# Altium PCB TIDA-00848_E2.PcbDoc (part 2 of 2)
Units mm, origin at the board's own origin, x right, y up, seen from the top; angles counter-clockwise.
Board outline 40 x 87.63 mm, 2 copper layers (Top Layer, Bottom Layer), stack 0.98 mm thick; 101 components, 66 nets, 314 pads, 292 vias.
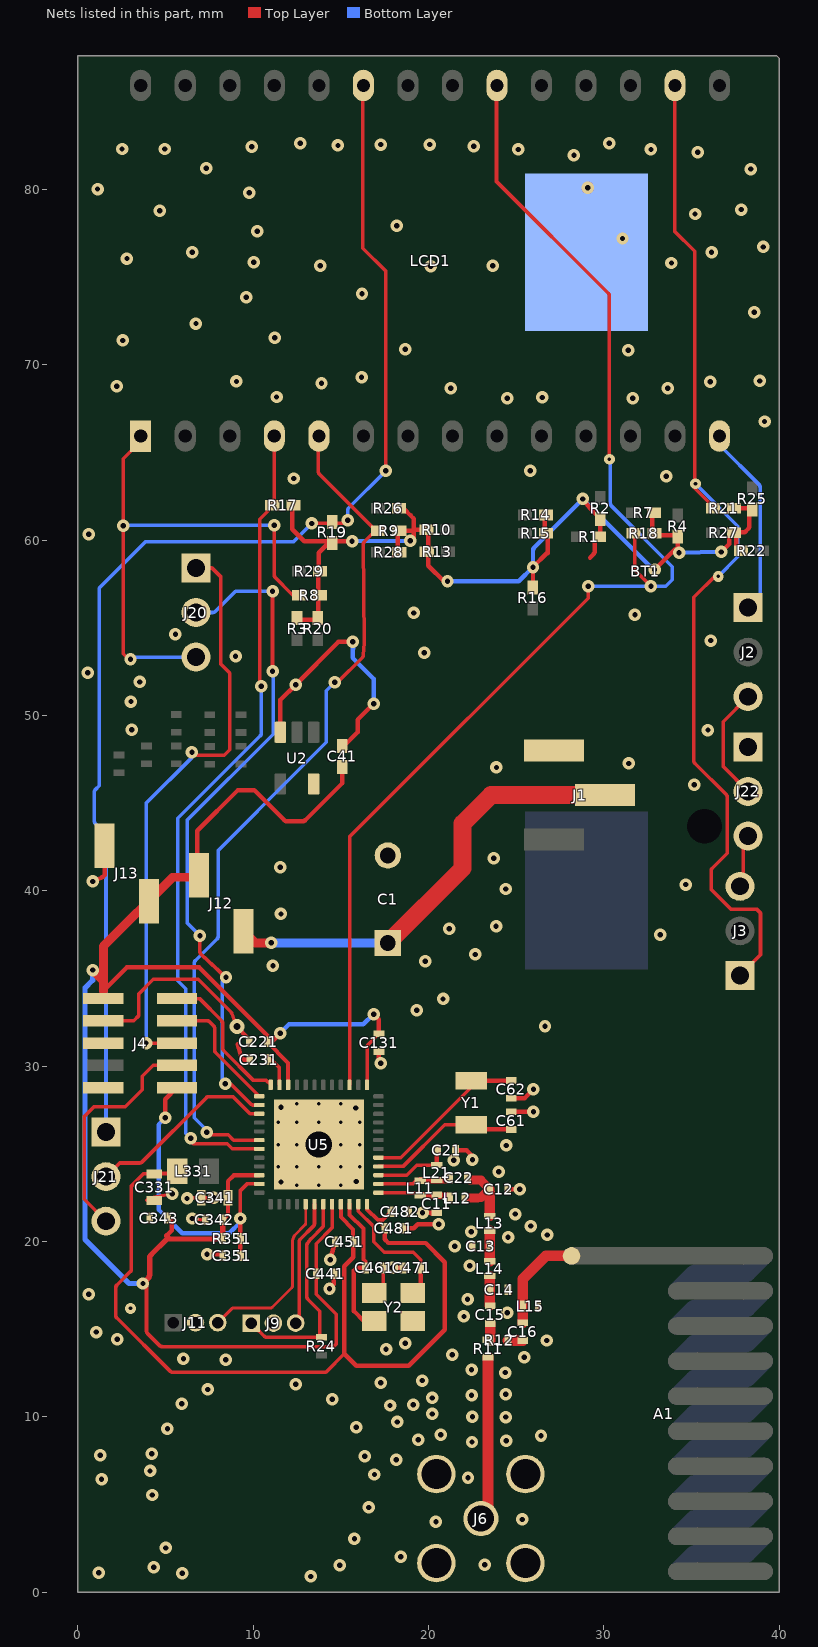
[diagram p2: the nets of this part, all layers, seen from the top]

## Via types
v1: diameter 0.711, hole 0.305, Top Layer to Bottom Layer, 239 vias
v2: diameter 0.5, hole 0.2, Top Layer to Bottom Layer, 21 vias
v3: diameter 1, hole 0.38, Top Layer to Bottom Layer, 19 vias
v4: diameter 0.61, hole 0.203, Top Layer to Bottom Layer, tented both sides, 8 vias
v5: diameter 3.175, hole 3.175, Top Layer to Bottom Layer, 2 vias
v6: diameter 0.864, hole 0.406, Top Layer to Bottom Layer, 1 vias
v7: diameter 1.27, hole 0.711, Top Layer to Bottom Layer, 1 vias
v8: diameter 1.9, hole 1.5, Top Layer to Bottom Layer, 1 vias

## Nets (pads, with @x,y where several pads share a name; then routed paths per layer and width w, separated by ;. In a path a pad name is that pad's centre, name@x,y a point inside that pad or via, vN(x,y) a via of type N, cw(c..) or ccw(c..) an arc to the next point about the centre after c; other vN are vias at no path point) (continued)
DIO_20: LCD1.5 R9.1 U5.30 | length 48.9
  Top Layer w0.203: v1@7.564,26.091 8.565,26.091 8.876,25.781 U5.30@10.345,25.781 ; LCD1.5@13.741,65.946 13.716,65.921 13.716,63.914 ccw(c13.919,63.914) 13.757,63.792 ccw(c13.919,63.914) 13.775,63.771 17.132,60.414 17.132,60.35 16.764,60.35 16.338,59.925 ccw(c16.482,59.781) 16.279,59.78 16.329,54.209 cw(c15.672,54.204) 16.328,54.161 16.281,53.437 cw(c16.078,53.45) 16.222,53.306 14.808,51.892 v1(14.656,51.892)
  Bottom Layer w0.203: v1@7.315,26.264 7.264,26.314 7.264,26.43 6.629,27.065 6.629,35.866 cw(c6.833,35.866) 6.67,35.988 cw(c6.833,35.866) 6.689,36.01 7.942,37.263 ccw(c7.798,37.406) 7.96,37.284 ccw(c7.798,37.406) 8.001,37.406 8.001,42.304 9.871,44.174 9.873,44.174 10.258,44.559 10.258,44.562 14.173,48.477 14.173,51.41 v1(14.656,51.892)
  other v1: 7.341,26.238
DIO_21: LCD1.4 R17.2 U5.31 | length 46.6
  Top Layer w0.203: 6.591,25.565 8.522,25.565 8.806,25.281 U5.31@10.345,25.281 ; v1(10.465,51.664) 10.38,51.749 10.38,61.205 11.176,62.001 11.189,62.014 11.189,65.933 LCD1.4@11.201,65.946
  Bottom Layer w0.203: v1(6.426,25.883) 6.147,26.162 6.147,34.418 5.691,34.874 5.691,44.138 10.406,48.852 ; 10.406,48.853 ccw(c10.262,48.995) 10.424,48.873 ccw(c10.262,48.995) 10.465,48.995 v1(10.465,51.664)
DIO_30: J9.1 R24.2 U5.43 | length 12.7
  Top Layer w0.203: J9.1@10.008,15.519 10.101,15.121 10.634,14.588 ccw(c10.778,14.732) 10.656,14.569 ccw(c10.778,14.732) 10.778,14.529 13.792,14.529 R24.2@13.894,14.529 13.792,14.63 13.792,16.027 13.115,16.704 ; 13.114,16.706 cw(c13.259,16.848) 13.056,16.848 13.056,19.779 cw(c13.259,19.779) 13.096,19.901 cw(c13.259,19.779) 13.098,19.903 13.271,20.125 cw(c13.589,19.877) 13.304,20.162 13.935,20.793 ccw(c13.792,20.937) 13.995,20.937 U5.43@13.995,22.131
GND: BT1.2 C1.2 C11.1 C12.2 C13.2 C14.2 C21.1 C41.2 C61.2 C62.2 C131.2 C221.2 C231.2 C331.2 C341.2 C342.2 C343.2 C351.2 C441.2 C451.2 C461.2 C471.2 C481.2 C482.2 J4.3 J4.5 J4.9 J6.2 J6.3 J6.4 J6.5 J9.2 J11.2 J13.2 J22.1 L15.1 U2.3 U5.49 Y2.2 Y2.4 | length 48.1
  Top Layer w0.2: Y2.4@16.909,17.056 17.424,17.572 C461.2@17.424,18.491 v1(17.932,18.491)
  Top Layer w0.203: J4.3@1.448,32.588 3.175,32.588 3.48,32.893 3.48,34.138 4.293,34.95 6.858,34.95 8.739,33.069 ; C331.2@3.937,22.352 4.032,22.447 4.073,22.479 cw(c4.176,22.304) 4.141,22.504 v1(5.385,22.722) ; v1(6.223,22.454) 6.274,22.504 C341.2@7.036,22.504 v1(7.747,22.504) v1@7.798,22.504 ; v1(6.528,21.311) 7.01,21.234 ; 8.74,33.068 cw(c8.596,32.925) 8.786,32.997 v6(9.068,32.258)
  Top Layer w0.254: v1(0.838,40.538) 1.37,40.766 ccw(c1.27,40.999) 1.449,40.819 1.524,40.894 J13.2@1.524,42.583 ; v1(7.366,19.279) 8.191,19.279 C351.2@8.255,19.177 ; v6(9.068,32.258) 9.716,31.572 C221.2@9.779,31.394 ; 9.119,31.242 9.306,30.565 ccw(c9.55,30.632) 9.371,30.453 9.445,30.378 C231.2@9.804,30.378 ; U2.3@11.547,49.049 11.547,50.891 v1(12.421,51.765) 14.859,54.204 v1(15.672,54.204) ; v1(14.351,17.297) 14.605,17.551 C441.2@14.605,18.161 ; v1(14.402,18.948) 14.618,19.812 C451.2@14.681,19.99 ; C41.2@15.088,48.184 15.951,49.047 15.951,49.759 v1(16.866,50.673) ; C131.2@17.17,30.836 17.17,30.302 17.297,30.175 v1(17.272,30.175) ; v1(17.932,18.491) C471.2@18.542,18.491 ; C481.2@18.517,20.752 19.152,20.752 19.38,20.98 v1(20.574,20.98) ; v1(19.66,21.641) 20.142,21.641 C11.1@20.193,21.59 ; C21.1@21.537,25.203 22.168,25.203 22.504,24.867 v1(22.504,24.663) ; C12.2@24.511,22.987 v1(25.197,22.987) ; C61.2@24.714,27.407 v1(25.984,27.407) ; C62.2@24.714,28.169 25.476,28.169 v1(25.984,28.677)
  Bottom Layer w0.254: 15.706,53.806 15.706,54.17 v1(15.672,54.204) 15.672,53.289 16.866,52.095 v1(16.866,50.673)
  other v1: 13.284,0.889 5.944,1.067 1.194,1.092 4.318,1.422 14.935,1.524 23.216,1.549 18.415,2.007 5.015,2.515 15.773,3.048 20.422,4.013 25.349,4.14 16.586,4.826 4.242,5.537 1.346,6.426 22.25,6.528 16.916,6.706 4.115,6.909 18.161,7.544 16.358,7.747 1.27,7.798 4.216,7.899 22.479,8.56 24.435,8.636 19.406,8.687 26.416,8.915 20.701,8.966 5.105,9.322 15.875,9.394 18.212,9.703 24.409,9.982 22.504,10.008 20.218,10.16 17.805,10.643 19.126,10.693 5.918,10.744 14.503,10.998 20.218,11.074 22.454,11.227 24.409,11.278 7.396,11.557 12.421,11.862 17.272,11.938 19.634,12.065 24.384,12.522 22.454,12.675 8.433,13.259 6.02,13.31 25.451,13.386 21.361,13.538 17.577,13.843 18.669,14.199 26.746,14.351 2.235,14.427 1.041,14.834 22.022,15.723 24.486,15.926 22.225,16.713 0.61,16.993 22.352,18.618 21.488,19.736 24.536,20.244 26.772,20.371 22.428,20.549 25.832,20.879 24.943,21.565 11.582,23.393 15.875,23.419 24.003,23.978 21.438,24.638 24.435,25.476 15.85,27.61 11.582,27.661 26.645,32.283 19.329,33.198 20.828,33.833 11.125,35.738 19.812,35.992 22.657,36.373 33.223,37.49 21.184,37.846 23.851,37.973 11.582,38.684 24.409,40.107 34.671,40.361 11.532,41.351 23.724,41.859 35.154,46.05 23.876,47.041 31.42,47.269 35.941,49.174 3.073,49.2 3.023,50.8 3.531,51.918 0.559,52.451 8.992,53.391 19.761,53.594 36.093,54.28 5.563,54.635 31.775,55.753 19.152,55.855 0.61,60.35 12.319,63.525 33.553,63.652 25.806,63.957 39.167,66.777 24.486,68.097 31.648,68.097 26.492,68.148 11.328,68.174 21.26,68.682 33.655,68.682 2.21,68.783 13.894,68.961 36.068,69.037 9.042,69.063 38.887,69.088 16.18,69.291 31.394,70.841 18.669,70.891 2.565,71.399 11.227,71.552 6.731,72.365 38.583,73 9.601,73.863 16.205,74.066 20.117,75.641 13.818,75.667 23.673,75.667 33.858,75.819 10.033,75.87 2.794,76.073 6.528,76.429 36.144,76.429 39.091,76.733 31.064,77.216 10.236,77.622 18.186,77.953 35.204,78.613 4.674,78.791 37.846,78.867 9.779,79.832 1.118,80.035 29.083,80.112 38.379,81.178 7.315,81.229 28.296,81.966 35.357,82.144 25.121,82.296 32.69,82.296 2.515,82.321 4.953,82.321 9.906,82.448 22.581,82.474 14.834,82.525 17.272,82.575 20.066,82.575 12.675,82.652 30.302,82.652
  other v2: 12.485,23.206 13.745,23.206 15.005,23.206 11.42,24.271 12.485,24.271 13.745,24.271 15.005,24.271 16.07,24.271 11.42,25.531 12.485,25.531 13.745,25.531 15.005,25.531 16.07,25.531 11.42,26.791 12.485,26.791 13.745,26.791 15.005,26.791 16.07,26.791 12.485,27.856 13.745,27.856 15.005,27.856
  other v4: 2.997,16.18
  other v8: 13.745,25.531
JTAG_TCK: J4.4 U5.25 | length 7.3
  Top Layer w0.203: J4.4@5.648,32.588 7.361,32.588 cw(c7.361,32.385) 7.483,32.548 cw(c7.361,32.385) 7.504,32.529 7.739,32.295 cw(c7.595,32.152) 7.757,32.273 cw(c7.595,32.152) 7.798,32.152 7.798,30.912 ccw(c8.001,30.912) 7.857,30.769 ; 7.857,30.769 U5.25@10.345,28.281
JTAG_TDI: J21.2 U5.27 | length 11
  Top Layer w0.203: J21.2@1.6,23.698 2.38,24.478 3.515,24.478 ccw(c3.515,24.681) 3.637,24.518 ccw(c3.515,24.681) 3.658,24.537 7.329,28.208 cw(c7.472,28.064) 7.35,28.226 cw(c7.472,28.064) 7.472,28.267 8.832,28.267 9.818,27.281 U5.27@10.345,27.281
JTAG_TDO: J20.2 U5.26 | length 38.3
  Top Layer w0.203: v1(6.96,37.44) 6.96,36.524 ccw(c7.163,36.524) 7.025,36.374 v1(8.446,35.065) ; v1(8.395,28.994) 8.617,28.994 cw(c8.617,28.791) 8.761,28.935 9.855,27.84 ccw(c9.999,27.984) 9.999,27.781 U5.26@10.345,27.781 ; v1(11.1,52.527) v1(11.1,57.099)
  Bottom Layer w0.203: J20.2@6.731,55.88 7.688,55.88 ccw(c7.688,56.083) 7.832,55.939 8.932,57.04 cw(c9.076,56.896) 8.954,57.059 cw(c9.076,56.896) 9.076,57.099 v1(11.1,57.099) ; v1(6.96,37.44) 6.223,38.176 6.223,44.02 11.138,48.935 v1@11.138,52.286 ; v1(8.395,28.994) 8.23,29.159 8.23,32.385 8.233,32.388 8.233,34.768 cw(c8.436,34.768) 8.292,34.911 v1(8.446,35.065)
JTAG_TMS: J4.2 U5.24 | length 8.3
  Top Layer w0.203: J4.2@5.648,33.858 6.934,33.858 8.195,32.597 cw(c8.052,32.453) 8.255,32.453 8.255,31.025 ccw(c8.458,31.025) 8.314,30.882 ; 8.315,30.882 10.011,29.185 10.741,29.185 U5.24@10.995,28.931
LCD_PIN_1: J20.3 LCD1.1 R8.1 | length 30.5
  Top Layer w0.203: v1(2.997,53.213) 2.896,53.213 2.591,53.518 v1(2.591,60.833) 2.591,64.655 3.581,65.646 LCD1.1@3.581,65.946 ; v1(11.201,60.858) 11.201,58.018 ccw(c11.405,58.018) 11.242,57.897 ccw(c11.405,58.018) 11.261,57.875 12.206,56.93 ccw(c12.349,57.074) 12.31,56.875 R8.1@12.608,56.871
  Bottom Layer w0.203: v1(2.591,60.833) 2.616,60.858 v1(11.201,60.858) ; v1(2.997,53.213) 3.124,53.34 J20.3@6.731,53.34
LCD_PIN_14: J2.1 LCD1.14 | length 11
  Bottom Layer w0.203: LCD1.14@36.601,65.946 ccw(c36.754,65.812) 36.551,65.813 36.551,65.565 ccw(c36.754,65.565) 36.61,65.422 38.853,63.179 cw(c38.71,63.035) 38.913,63.035 38.913,56.883 J2.1@38.227,56.159
LCD_PIN_16: J3.1 LCD1.16 R21.2 | length 58.9
  Top Layer w0.203: LCD1.16@34.061,85.946 34.036,85.921 34.036,77.622 35.179,76.479 35.179,62.967 R21.2@36.322,61.824 ; 36.177,40.023 cw(c36.322,40.165) 36.119,40.165 36.119,41.14 cw(c36.322,41.14) 36.159,41.262 cw(c36.322,41.14) 36.177,41.283 37.036,42.142 37.036,45.353 ccw(c36.833,45.353) 36.996,45.475 ccw(c36.833,45.353) 36.977,45.496 35.187,47.286 cw(c35.331,47.43) 35.169,47.308 cw(c35.331,47.43) 35.128,47.43 35.128,56.744 v4@36.424,58.039 ; 36.178,40.022 37.236,38.964 38.71,38.964 38.938,38.735 38.938,36.347 J3.1@37.77,35.179
  Bottom Layer w0.203: v4(35.23,63.221) 37.644,60.807 37.644,59.056 v4(36.525,57.937)
LCD_PIN_20: LCD1.20 R18.2 U5.15 | length 74.7
  Top Layer w0.203: U5.15@15.495,28.931 15.495,43.079 29.108,56.693 v1(29.108,57.379) ; LCD1.20@23.901,85.946 23.876,85.921 23.876,80.467 30.259,74.084 cw(c30.115,73.941) 30.318,73.941 v4(30.318,64.622) ; R18.2@31.775,60.515 31.775,58.293 v1(32.69,57.379)
  Bottom Layer w0.203: v1(29.108,57.379) v1(32.69,57.379) 33.528,57.379 33.901,57.752 33.901,58.491 30.438,61.955 ; v4@30.378,64.491 30.378,62.098 ccw(c30.582,62.098) 30.437,61.955
LCD_PIN_23: J21.1 LCD1.23 R19.2 | length 73.4
  Top Layer w0.203: v1(13.335,60.96) 14.503,60.96 15.215,60.96 v1(15.392,61.138) ; LCD1.23@16.256,85.921 16.256,76.657 17.551,75.362 v1(17.551,63.957)
  Bottom Layer w0.203: 0.998,43.833 cw(c1.143,43.975) 0.94,43.975 0.94,45.639 cw(c1.143,45.639) 0.98,45.761 cw(c1.143,45.639) 0.998,45.782 1.216,45.999 1.216,57.274 3.848,59.906 12.281,59.906 v1(13.335,60.96) ; 0.999,43.832 1.6,43.231 J21.1@1.6,26.238 ; v1(15.392,61.138) 15.392,61.714 cw(c15.596,61.714) 15.452,61.858 v1(17.551,63.957)
NetA1_1: A1.1 C16.1 L15.2 | length 5.8
  Top Layer w0.61: C16.1@25.375,15.367 25.375,17.854 26.697,19.177 A1.1@28.155,19.177
NetC11_2: C11.2 L11.2 L12.1 U5.1 | length 4.2
  Top Layer w0.203: U5.1@17.145,22.781 19.397,22.781 L11.2@19.533,22.645
  Top Layer w0.254: 20.154,22.645 C11.2@20.193,22.606 ; L12.1@21.082,22.606 L12.1@21.209,22.479
  Top Layer w0.356: L11.2@19.533,22.645 20.154,22.645 ; C11.2@20.193,22.606 L12.1@21.082,22.606
NetC12_1: C12.1 C22.2 L12.2 L13.1 | length 4.6
  Top Layer w0.254: C22.2@22.225,23.622 C22.2@22.352,23.495 ; C12.1@23.399,22.891 C12.1@23.495,22.795
  Top Layer w0.3: L12.2@22.059,22.479 22.53,22.479
  Top Layer w0.508: 22.327,22.479 22.784,22.479 ; C22.2@22.352,23.495 22.987,23.495 C12.1@23.495,22.987 C12.1@23.399,22.891 ; 22.987,22.504 C12.1@23.399,22.916
  Top Layer w0.61: L13.1@23.495,21.463 C12.1@23.495,22.795
NetC13_1: C13.1 L13.2 L14.1 | length 1.7
  Top Layer w0.61: L14.1@23.495,18.872 C13.1@23.495,19.736 L13.2@23.495,20.613
NetC14_1: C14.1 C15.1 L14.2 | length 1.7
  Top Layer w0.508: C15.1@23.495,16.358 C15.1@23.52,16.332
  Top Layer w0.61: C15.1@23.495,16.358 L14.2@23.495,18.022
NetC15_2: C15.2 R11.1 R12.1 | length 1
  Top Layer w0.61: R12.1@23.52,14.351 C15.2@23.52,15.316
NetC16_2: C16.2 R12.2 | length 0.8
  Top Layer w0.61: R12.2@24.536,14.351 C16.2@25.375,14.351
NetC21_2: C21.2 L21.1 U5.3 | length 4.4
  Top Layer w0.203: U5.3@17.145,23.781 18.759,23.781 19.33,24.352 L21.1@20.472,24.352
  Top Layer w0.254: L21.1@20.472,24.352 20.472,25.154 C21.2@20.521,25.203
NetC22_1: C22.1 L11.1 L21.2 U5.2 | length 4.2
  Top Layer w0.203: U5.2@17.145,23.281 19.09,23.281 19.304,23.495 L11.1@19.533,23.495
  Top Layer w0.254: C22.1@21.082,23.495 C22.1@21.209,23.622
  Top Layer w0.356: L11.1@19.533,23.495 C22.1@21.082,23.495
NetC61_1: C61.1 U5.4 Y1.1 | length 8.7
  Top Layer w0.203: U5.4@17.145,24.281 18.548,24.281 20.931,26.665 Y1.1@22.428,26.665
  Top Layer w0.254: Y1.1@22.428,26.665 22.702,26.391 C61.1@24.714,26.391
NetC62_1: C62.1 U5.5 Y1.2 | length 9.6
  Top Layer w0.203: U5.5@17.145,24.781 18.406,24.781 22.428,28.804 Y1.2@22.428,29.165
  Top Layer w0.254: Y1.2@22.428,29.165 24.694,29.165 C62.1@24.714,29.185
NetC231_1: C231.1 U5.23 | length 1.9
  Top Layer w0.2: C231.1@10.82,30.378 11.024,30.378 11.495,29.907 U5.23@11.495,28.931
  Top Layer w0.254: C231.1@10.795,30.48 C231.1@10.858,30.416
NetC461_1: C461.1 U5.46 Y2.1 | length 8.5
  Top Layer w0.229: U5.46@15.495,22.131 15.495,21.513 16.281,20.726 16.281,18.974 16.408,18.847 C461.1@16.408,18.491
  Top Layer w0.254: C461.1@16.408,18.491 15.893,18.491 15.745,18.343 15.745,16.031 16.319,15.456 Y2.1@16.909,15.456
NetC471_1: C471.1 U5.47 Y2.3 | length 7.9
  Top Layer w0.203: U5.47@15.995,22.131 15.995,21.724 16.866,20.853 16.866,19.99 17.475,19.38 19.126,19.38 19.558,18.948 C471.1@19.558,18.491
  Top Layer w0.254: Y2.3@18.837,17.272 Y2.3@18.837,17.501 ; Y2.3@19.109,17.056 19.558,17.505 C471.1@19.558,18.491
NetJ6_1: J6.1 R11.2 | length 9.4
  Top Layer w0.61: J6.1@22.987,4.191 23.393,4.597 R11.2@23.393,13.386
NRESET: C351.1 J4.10 R351.1 U5.35 | length 18.1
  Top Layer w0.203: v1@9.373,21.209 v1(9.271,21.311) 9.271,22.911 9.641,23.281 U5.35@10.345,23.281
  Top Layer w0.254: v1(4.978,27.051) 4.978,28.109 J4.10@5.648,28.778 ; C351.1@9.271,19.177 R351.1@9.271,20.168 9.271,21.107 v1@9.373,21.209
  Bottom Layer w0.254: v1(4.978,27.051) 4.597,26.67 4.597,21.819 5.949,20.467 8.631,20.467 9.271,21.107 v1(9.271,21.311)
SEG_BASE_COMMON: R1.2 R2.2 R3.2 R4.2 R7.2 R8.2 R9.2 R10.2 R13.2 R14.2 R15.1 R16.1 R17.1 R18.1 R19.1 R20.1 R21.1 R22.1 R25.1 R26.1 R27.1 R28.2 R29.1 | length 61.4
  Top Layer w0.254: R17.1@12.192,62.001 12.217,61.976 12.217,60.63 12.903,59.944 R19.1@14.503,59.944 ; R3.2@12.497,55.474 13.691,55.474 13.716,55.499 R8.2@13.716,56.871 ; R8.2@13.716,56.972 13.716,58.242 13.732,58.258 13.732,59.287 14.389,59.944 R19.1@14.503,59.944 ; v1(15.638,59.944) R19.1@14.503,59.944 ; R26.1@18.212,61.824 18.275,61.849 18.437,61.849 cw(c18.437,61.595) 18.616,61.775 18.974,61.417 19.152,61.239 19.152,60.554 ; R28.2@18.291,59.255 18.237,59.309 18.237,60.554 19.152,60.554 ; v1(18.948,59.969) 18.974,59.969 19.152,60.147 19.152,60.554 ; v1(21.082,57.658) 20.879,57.658 19.99,58.547 19.99,60.579 19.964,60.604 19.202,60.604 19.152,60.554 ; R16.1@25.933,57.318 25.959,57.591 v1(25.959,58.471) 26.749,59.261 26.811,59.261 26.811,60.401 26.619,60.401 R14.2@26.619,61.443 ; v1(28.804,62.357) 29.24,61.818 ccw(c29.494,62.024) 29.259,61.796 29.621,61.422 R2.2@29.794,61.224 29.794,60.376 R1.2@29.845,60.325 ; 29.21,59.004 29.41,59.204 ccw(c29.23,59.383) 29.484,59.383 29.484,59.843 cw(c29.738,59.843) 29.558,60.022 R1.2@29.734,60.198 ; R7.2@32.766,61.57 32.766,60.427 32.893,60.3 34.214,60.3 34.214,59.36 v1(34.29,59.284) ; v1(32.893,58.318) v1@34.074,59.499 ; v1(36.703,59.334) 37.157,59.788 37.157,60.254 37.178,60.274 37.537,60.274 37.557,60.254 37.557,59.584 37.73,59.411 R22.1@37.83,59.411 ; R27.1@37.43,60.427 37.455,60.452 38.033,60.452 38.229,60.648 ccw(c38.049,60.827) 38.303,60.827 R25.1@38.303,61.672 ; R21.1@37.43,61.824 38.389,61.824 R25.1@38.456,61.757
  Bottom Layer w0.254: v1(15.638,59.944) v1(18.948,59.969) ; v1(21.082,57.658) 25.146,57.658 v1(25.959,58.471) 25.959,59.407 cw(c26.213,59.407) 26.01,59.559 cw(c26.213,59.407) 26.033,59.587 v1(28.804,62.357) 32.777,58.384 ccw(c32.955,58.565) v1(32.893,58.318) ; v1(34.29,59.284) v1(36.703,59.334)
TDI: J4.8 J21.3 | length 13.4
  Top Layer w0.203: J21.3@1.6,21.158 0.356,22.403 0.356,27.127 0.914,27.686 2.692,27.686 3.659,28.653 3.659,29.416 4.291,30.048 J4.8@5.648,30.048
TDO: J4.6 J20.1 | length 33.5
  Top Layer w0.203: v1(3.886,31.318) J4.6@5.648,31.318 ; v1(6.502,47.904) 6.664,47.743 8.347,47.743 8.658,48.054 8.658,52.426 8.157,52.927 8.157,57.909 7.645,58.42 J20.1@6.731,58.42
  Bottom Layer w0.203: v1(3.886,31.318) 3.886,44.997 6.502,47.613 v1(6.502,47.904)
TMP63_AIN1: J11.3 U5.41 | length 10.1
  Top Layer w0.17: J11.3@7.976,15.367 8.769,16.16 cw(c8.889,16.04) 8.889,16.21 10.983,16.21 ccw(c10.983,16.38) 11.103,16.259 12.187,17.344 ccw(c12.067,17.464) 12.237,17.464 12.237,19.982 cw(c12.827,19.982) 12.319,20.282 ; 12.32,20.283 cw(c12.827,19.982) 12.355,20.336 cw(c12.827,19.982) 12.407,20.395 cw(c12.827,19.982) 12.408,20.397 cw(c12.683,20.125) 12.409,20.398 12.945,20.934 ccw(c12.825,21.054) 12.995,21.054 U5.41@12.995,22.131
TMP63_ISRC2: J9.3 U5.42 | length 7
  Top Layer w0.203: J9.3@12.806,15.535 12.797,15.531 ccw(c12.615,15.439) 12.759,15.583 12.683,15.658 cw(c12.827,15.802) 12.624,15.802 12.624,19.982 cw(c12.827,19.982) 12.664,20.104 cw(c12.827,19.982) 12.682,20.124 13.436,20.878 ccw(c13.292,21.021) 13.454,20.899 ccw(c13.292,21.021) 13.495,21.021 U5.42@13.495,22.131
UART_RX: J2.3 J22.2 | length 6.9
  Top Layer w0.203: J22.2@38.227,45.669 36.805,47.092 36.805,49.657 J2.3@38.227,51.079
  Bottom Layer w0.203: J2.3@37.922,51.079 J2.3@38.227,51.079
UART_TX: J3.3 J22.3 | length 3
  Top Layer w0.203: J3.3@37.77,40.259 37.9,40.389 ccw(c37.756,40.533) 37.959,40.533 37.959,42.777 cw(c38.163,42.777) 38.019,42.921 J22.3@38.227,43.129
VCC_430: U2.5
VCC_EXTERN: J1.3
VCC_IN: C1.1 J1.2 J12.1 | length 25.9
  Top Layer w0.508: J12.1@9.449,37.706 10.122,37.033 v1(11.024,37.033)
  Top Layer w1.016: C1.1@17.678,37.022 21.946,41.29 21.946,43.84 23.571,45.466 J1.2@30.074,45.466
  Bottom Layer w0.508: v1(11.024,37.033) 11.034,37.022 C1.1@17.678,37.022
VDDR: C331.1 C451.1 C481.1 C482.1 L331.2 U5.45 U5.48 | length 52.3
  Top Layer w0.203: C331.1@4.343,23.851 3.734,23.851 3.051,23.168 3.051,18.426 cw(c2.848,18.426) 3.011,18.304 cw(c2.848,18.426) 2.992,18.283 2.218,17.509 ccw(c2.362,17.366) 2.2,17.488 ccw(c2.362,17.366) 2.159,17.366 2.159,15.78 ccw(c2.362,15.781) 2.218,15.639 5.25,12.606 ccw(c5.393,12.751) 5.391,12.548 14.148,12.548 15.189,13.589
  Top Layer w0.229: U5.45@14.995,22.131 14.995,21.389 15.697,20.687 C451.1@15.697,19.99 ; U5.48@16.495,22.131 16.495,21.834 17.107,21.222 ; C481.1@17.501,20.752 17.501,20.828 17.107,21.222 ; C482.1@17.856,21.692 17.386,21.222 17.107,21.222
  Top Layer w0.254: C331.1@4.343,23.876 5.182,23.876 L331.2@5.309,24.003 ; C451.1@15.697,19.99 15.697,19.093 15.189,18.585 15.189,13.589 15.875,12.903 18.872,12.903 20.93,14.961 20.93,18.821 19.837,19.914 17.711,19.914 17.501,20.124 C481.1@17.501,20.752
VDDS: C41.1 C131.1 C221.1 C341.1 C342.1 C343.1 C441.1 J4.1 J12.2 J13.1 R351.2 U5.13 U5.22 U5.34 U5.44 | length 106.2
  Top Layer w0.2: U5.13@16.495,28.931 16.495,31.176 C131.1@17.17,31.852
  Top Layer w0.203: v1@3.912,17.501 3.912,14.892 ccw(c4.115,14.892) 3.952,14.77 ccw(c4.115,14.892) 3.971,14.749 4.656,14.064 ccw(c4.799,14.208) 4.677,14.045 ccw(c4.799,14.208) 4.799,14.005 14.589,14.005 14.732,14.148 14.732,15.85 13.589,16.993 13.589,19.877 14.495,20.783 U5.44@14.495,22.131
  Top Layer w0.229: C221.1@10.795,31.394 11.995,30.194 U5.22@11.995,28.931
  Top Layer w0.254: 1.448,34.29 2.794,35.636 6.909,35.636 10.795,31.75 ; 5.055,20.32 5.359,20.625 5.359,21.336 ; J12.2@6.807,40.78 6.807,43.434 9.126,45.753 10.051,45.753 11.762,44.042 ccw(c11.942,44.221) 11.942,43.967 12.798,43.967 ccw(c12.798,44.221) 12.95,44.018 ccw(c12.798,44.221) 12.977,44.041 15.088,46.152 C41.1@15.088,47.168 ; C342.1@8.28,21.234 8.56,21.514 C341.1@8.56,22.504 8.56,23.444 8.897,23.781 U5.34@10.345,23.781 ; C221.1@10.795,31.394 11.049,31.394 v1(11.532,31.877) ; v1(16.866,32.969) 17.17,32.664 C131.1@17.17,31.852
  Top Layer w0.305: v1(3.708,17.602) 4.001,17.895 ccw(c3.785,18.109) 4.089,18.109 4.089,19.025 cw(c4.394,19.025) 4.15,19.208 cw(c4.394,19.025) 4.179,19.241 5.08,20.142 5.232,20.142 ; 5.055,20.32 5.232,20.142 ; C342.1@8.28,21.234 8.255,21.209 R351.2@8.255,20.168 8.23,20.142 5.232,20.142
  Top Layer w0.508: v1(0.838,35.484) 1.448,34.874 ; 1.448,34.29 1.448,34.874 ; J12.2@6.807,40.78 5.397,40.78 1.448,36.83 1.448,34.874
  Bottom Layer w0.254: v1(11.532,31.877) 12.04,32.385 16.281,32.385 v1(16.866,32.969)
  Bottom Layer w0.305: v1(0.838,35.484) 0.838,34.9 0.406,34.468 0.406,20.117 2.921,17.602 v1(3.708,17.602)
pads on no net: A1. BT1.0 FID1.1 FID2.1 FID3.1 H9.0 H10.0 H11.0 J4.7 LCD1.17 LCD1.18 LCD1.19 U2.1
copper on no net: | length 1403.3
  Top Layer w0.254: -60.198,875.792 -60.198,2279.142
  other v3: 34.155,1.177 39.155,1.177 34.155,3.177 39.155,3.177 34.155,5.177 39.155,5.177 34.155,7.177 39.155,7.177 34.155,9.177 39.155,9.177 34.155,11.177 39.155,11.177 34.155,13.177 39.155,13.177 34.155,15.177 39.155,15.177 34.155,17.177 39.155,17.177 39.155,19.177
  other v5: 2.413,3.632 37.313,31.318

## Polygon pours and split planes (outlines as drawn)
GND on Bottom Layer "Bottom Layer-GND_Corner" (solid, remove dead copper, pour order 13): 0.152,11.557 0.152,0.229 0.229,0.305 4.597,0.305 4.597,11.557 0.152,11.557
GND on Bottom Layer "Bottom Layer- GND SMA" (solid, remove dead copper, pour order 11): 15.85,11.557 15.85,0.279 27.127,0.279 27.127,11.557 15.85,11.557
GND on Bottom Layer "Bottom Layer- GND1310" (solid, remove dead copper, pour order 14): 0.152,64.414 0.152,11.506 27.153,11.506 27.153,33.655 39.726,33.655 39.726,64.414
GND on Bottom Layer "Bottom Layer-GND" (hatched 45Degree grid 0.762 track 0.203, pour order 9): 4.572,11.354 4.572,11.557 15.875,11.557 15.875,0.66 15.875,0.305 4.572,0.305 4.572,11.43 4.572,11.481
GND on Bottom Layer "Bottom Layer-GND_LCD" (solid, remove dead copper, pour order 15): 0.229,87.325 0.229,64.211 39.751,64.211 39.751,87.3 0.203,87.3
GND on Top Layer "Top Layer-GND" (solid, pour order 10): 0.203,87.3 0.203,0.305 27.203,0.305 27.203,33.655 27.229,33.68 39.726,33.68 39.726,87.3 0.152,87.3

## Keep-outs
Keep-Out Layer:
  text ".Layer_Name" at -80.594,-38.57 h1.52

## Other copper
Top Layer:
  region net CAP_EL: 10.336,2.287 cw(c10.336,6.24) 6.383,6.24 cw(c10.336,6.24) 10.336,10.193 cw(c10.336,6.24) 14.289,6.24 cw(c10.336,6.24)
  text ".Layer_Name" at -80.594,-38.57 h1.52
Bottom Layer:
  text ".Layer_Name" at -80.594,-38.57 h1.52

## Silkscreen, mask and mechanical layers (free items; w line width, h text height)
Top Overlay:
  text "TIDA-00848 E2" at 17.958,50.8 h1.43
  text ".Layer_Name" at -80.594,-38.57 h1.52
Bottom Overlay:
  text ".Layer_Name" at -80.594,-38.57 h1.52
Top Paste:
  text ".Layer_Name" at -80.594,-38.57 h1.52
Bottom Paste:
  text ".Layer_Name" at -80.594,-38.57 h1.52
Top Solder:
  text ".Layer_Name" at -80.594,-38.57 h1.52
  text ".Layer_Name" at -80.594,-38.57 h1.52
Bottom Solder:
  text ".Layer_Name" at -80.594,-38.57 h1.52
Drill Guide:
  text ".Layer_Name" at -80.594,-38.57 h1.52
M1 Board Outline:
  lines w0.254: 39.929,87.63 0,87.63 0,0 40,0 40,87.508
  text ".Layer_Name" at -80.594,-38.57 h1.52
M2 Board Dimensions:
  rectangle: -95.25,-23.749 -92.075,-20.574
  rectangle: -92.075,-26.924 -82.55,-23.749
  lines w0.178: -95.25,-23.749 -69.85,-23.749 ; -92.075,-26.924 -92.075,-20.574 ; -88.9,-26.924 -88.9,-20.574 ; -82.55,-26.924 -82.55,-20.574 ; -76.2,-26.924 -76.2,-20.574 ; -95.25,-26.924 -69.85,-26.924 -69.85,-20.574 -95.25,-20.574 -95.25,-26.924
  lines w0.254: 0,0 0,87.63 ; 39.878,0.122 39.878,87.63
  text ".Layer_Name" at -80.594,-38.57 h1.52
M3 3D STEP Top:
  text ".Layer_Name" at -80.594,-38.57 h1.52
M4 3D STEP Bottom:
  text ".Layer_Name" at -80.594,-38.57 h1.52
M5 Assembly Top:
  lines w0.254: -102.667,-40.39 64.973,-40.39 ; -102.667,-35.226 65.024,-35.226 ; -102.667,-30.061 -102.667,-45.555 -0.94,-45.555 65.024,-45.555 65.024,-30.061 -102.654,-30.061 -102.654,-45.555 -62.636,-45.555 ; -40.056,-45.555 -40.056,-30.061 ; -7.874,-35.226 -7.874,-30.061 ; 13.462,-35.226 13.462,-30.061 ; 29.261,-45.72 29.261,-40.568
  text "COMPONENTS MARKED 'DNP' SHOULD NOT BE POPULATED." at -65.951,-24.854 h1.52
  text "ASSEMBLY VARIANT:" at -65.964,-27.788 h1.52
  text ".VariantName" at -39.649,-27.788 h1.52
  text "PCB VIEWED FROM TOP SIDE" at -101.054,-33.418 h1.52
  text "BOARD #:" at -38.151,-33.418 h1.52
  text ".PRJ_Number" at -24.295,-33.418 h1.52
  text "REV:" at -2.845,-33.418 h1.52
  text ".PCB_Rev" at 4.559,-33.418 h1.52
  text "SVN REV:" at 18.44,-33.418 h1.52
  text ".VersionControl_RevNumber" at 31.293,-33.418 h1.52
  text "TID #:" at -38.151,-38.583 h1.52
  text ".TID" at -24.295,-38.583 h1.52
  text "PLOT NAME =" at -101.054,-43.798 h1.52
  text ".plot_File_Name" at -80.594,-43.798 h1.52
  text "GENERATED    :" at -38.1,-43.798 h1.52
  text ".Print_Date" at -16.015,-43.798 h1.52
  text ".Print_Time" at 2.502,-43.798 h1.52
  text "TEXAS INSTRUMENTS" at 34.62,-43.798 h1.52
M6 Assembly Bottom:
  lines w0.254: -102.679,-35.238 65.011,-35.238 ; -102.629,-40.403 65.011,-40.403 ; -66.916,-45.733 -66.916,-40.581 ; -51.117,-35.238 -51.117,-30.074 ; -29.781,-35.238 -29.781,-30.074 ; 2.4,-45.568 2.4,-30.074 ; 24.981,-45.568 64.999,-45.568 64.999,-30.074 -102.679,-30.074 -102.679,-45.568 -36.716,-45.568 65.011,-45.568 65.011,-30.074
  text "COMPONENTS MARKED 'DNP' SHOULD NOT BE POPULATED." at 59.741,-24.841 h1.52
  text ".VariantName" at 33.223,-27.788 h1.52
  text "ASSEMBLY VARIANT:" at 59.614,-27.788 h1.52
  text ".VersionControl_RevNumber" at -68.948,-33.431 h1.52
  text "SVN REV:" at -56.096,-33.431 h1.52
  text ".PCB_Rev" at -42.215,-33.431 h1.52
  text "REV:" at -34.811,-33.431 h1.52
  text ".PRJ_Number" at -13.36,-33.431 h1.52
  text "BOARD #:" at 0.495,-33.431 h1.52
  text "PCB VIEWED FROM BOTTOM SIDE" at 63.398,-33.431 h1.52
  text ".TID" at -13.36,-38.595 h1.52
  text "TID #:" at 0.495,-38.595 h1.52
  text "TEXAS INSTRUMENTS" at -72.276,-43.811 h1.52
  text ".Print_Time" at -40.157,-43.811 h1.52
  text ".Print_Date" at -21.641,-43.811 h1.52
  text "GENERATED    :" at 0.445,-43.811 h1.52
  text ".plot_File_Name" at 42.939,-43.811 h1.52
  text "PLOT NAME =" at 63.398,-43.811 h1.52
M9 Title Sheet:
  drawing of 57 lines, arcs and shapes, not listed
  text "1" at -76.458,187.363 h1.78
  text "2" at -13.068,187.363 h1.78
  text "3" at 50.161,187.363 h1.78
  text "4" at 113.83,187.363 h1.78
  text "5" at 177.305,187.363 h1.78
  text "6" at 240.932,187.363 h1.78
  text "A" at -105.829,158.331 h1.78
  text "A" at 270.091,158.331 h1.78
  text "B" at -105.829,97.879 h1.78
  text "B" at 270.091,97.879 h1.78
  text "C" at -105.829,37.554 h1.78
  text "C" at 270.091,37.554 h1.78
  text "PROJECT TITLE:" at 192.875,-9.716 h1.14
  text ".PRJ_Title" at 194.145,-13.102 h1.78
  text "DESIGNED FOR:" at 192.875,-17.361 h1.14
  text ".PRJ_Customer" at 194.145,-20.917 h1.78
  text "D" at -105.829,-22.644 h1.78
  text "D" at 270.091,-22.644 h1.78
  text "FILE NAME:" at 192.875,-24.981 h1.14
  text ".PCB_File_Name_No_Path" at 194.145,-28.029 h1.78
  text "Texas Instruments (TI) and/or its licensors do not warrant the accuracy or completeness of this specification" at 66.65,-32.14 h1.14
  text "ENGINEER:" at 192.875,-32.347 h1.14
  text "LAYOUT BY:" at 231.102,-32.347 h1.14
  text "or any information contained therein. TI and/or its licensors do not warrant that this design will meet" at 65.507,-35.001 h1.14
  text ".PRJ_Engineer" at 194.145,-36.284 h1.78
  text ".PCB_Layout" at 232.385,-36.284 h1.78
  text "the specifications, will be suitable for your application or fit for any particular purpose, or will operate in" at 65.507,-37.863 h1.14
  text ".Layer_Name" at -80.594,-38.57 h1.52
  text "ALTIUM DESIGNER VERSION:" at 231.102,-40.221 h1.14
  text "an implementation. TI and/or its licensors do not warrant that the design is production worthy. You should" at 65.507,-40.725 h1.14
  text "completely validate and test your design implementation to confirm the system functionality for your application." at 66.65,-43.586 h1.14
  text ".print_Scale" at 194.145,-43.607 h1.78
  text ".Application_BuildNumber" at 232.385,-43.607 h1.78
  text "1" at -76.458,-48.857 h1.78
  text "2" at -13.068,-48.857 h1.78
  text "3" at 50.161,-48.857 h1.78
  text "4" at 113.83,-48.857 h1.78
  text "5" at 177.305,-48.857 h1.78
  text "6" at 240.932,-48.857 h1.78
M10 Fab Notes:
  drawing of 185 lines, arcs and shapes, not listed
  text "DESIGN INFORMATION" at 219.228,133.35 h1.52
  text "MIN. TRACK WIDTH:" at 202.856,128.778 h1.52
  text "8" at 230.701,128.778 h1.52
  text "MIL" at 234.631,128.778 h1.52
  text "MIN. CLEARANCE:" at 202.856,125.425 h1.52
  text "0.2" at 229.177,125.425 h1.52
  text "mm" at 234.631,125.425 h1.52
  text "MIN. VIA PAD SIZE:" at 202.856,122.072 h1.52
  text "24" at 229.939,122.072 h1.52
  text "MIL" at 234.631,122.072 h1.52
  text "0.05mm (2MIL)" at 220.509,118.473 h1.52
  text "MINIMUM ANNULAR RING" at 194.494,118.364 h1.52
  text "EXTERNAL" at 238.492,118.364 h1.52
  text "PER" at 199.574,115.367 h1.52
  text "IPC-D-275 CLASS 2 LEVEL C" at 205.162,115.367 h1.52
  text "MIL, HOLES" at 242.963,112.515 h1.52
  text "+/-" at 232.994,112.497 h1.52
  text "+/-" at 254.686,112.497 h1.52
  text "REGISTRATION TOLERANCES:" at 194.494,112.37 h1.52
  text "METAL" at 224.968,112.37 h1.52
  text "5" at 239.603,112.37 h1.52
  text "3" at 260.762,112.37 h1.52
  text "MIL" at 263.714,112.37 h1.52
  text "MATERIAL:" at 192.594,107.049 h1.52
  text "FR-4 High Tg" at 217.65,103.485 h1.52
  text "FR-408" at 203.288,103.267 h1.52
  text "X" at 213.753,103.267 h1.52
  text "OTHER" at 241.083,103.267 h1.52
  text "62 MIL (1.6mm) +/-10%" at 211.418,99.134 h1.52
  text "THICKNESS:" at 194.494,99.025 h1.52
  text "X" at 208.163,99.025 h1.52
  text "OTHER" at 244.055,99.025 h1.52
  text "TOLERANCE:" at 194.494,95.012 h1.52
  text "X" at 215.812,95.012 h1.52
  text "ANSI IPC-6012 TYPE 3 CLASS 2" at 220.56,95.012 h1.52
  text "OTHER +/-" at 220.56,91.05 h1.52
  text "BOW & TWIST:" at 194.494,87.062 h1.52
  text "X" at 215.812,87.062 h1.52
  text "ANSI IPC-6012 TYPE 3 CLASS 2" at 220.56,87.062 h1.52
  text "OTHER +/-" at 220.56,83.036 h1.52
  text "DRILLING:" at 192.594,79.518 h1.52
  text "REFERENCE:" at 194.494,76.546 h1.52
  text "X" at 210.959,76.546 h1.52
  text "AS SHOWN" at 215.708,76.546 h1.52
  text "X" at 233.844,76.546 h1.52
  text "NC_DRILL FILES" at 237.324,76.546 h1.52
  text "PTH MIN COPPER THICKNESS:" at 194.494,72.533 h1.52
  text "X" at 228.789,72.533 h1.52
  text "1MIL" at 232.269,72.533 h1.52
  text "OTHER" at 244.893,72.533 h1.52
  text "BOARD FINISH:" at 192.594,68.495 h1.52
  text "SILKSCREEN:" at 196.537,65.497 h1.52
  text "X" at 220.636,65.497 h1.52
  text "TOP" at 223.836,65.497 h1.52
  text "X" at 233.59,65.497 h1.52
  text "BOTTOM" at 236.816,65.497 h1.52
  text "SILKSCREEN COLOR:" at 196.537,61.256 h1.52
  text "X" at 220.61,61.256 h1.52
  text "WHITE" at 223.836,61.256 h1.52
  text "OTHER" at 236.816,61.256 h1.52
  text "SOLDER RESIST COLOR:" at 196.537,56.938 h1.52
  text "X" at 210.958,52.894 h1.52
  text "GREEN" at 214.184,52.894 h1.52
  text "BLUE" at 229.196,52.894 h1.52
  text "OTHER" at 242.861,52.894 h1.52
  text "IMMERSION GOLD (ENIG)" at 219.544,48.106 h1.52
  text "ENEPIG" at 253.517,48.022 h1.52
  text "SURFACE FINISH:" at 192.594,47.997 h1.52
  text "X" at 214.795,47.997 h1.52
  text "IMM. TIN/SILVER OR EQUIV" at 200.965,44.009 h1.52
  text "OTHER" at 237.324,44.009 h1.52
  text "ARRAY/PANEL:" at 192.594,39.462 h1.52
  text "CUT AND TRIM PER MECH LAYER 1" at 219.544,39.354 h1.52
  text "N.C. ROUTE" at 219.544,35.5 h1.52
  text "X" at 236.79,35.5 h1.52
  text "V. SCORE" at 241.54,35.5 h1.52
  text "CERTIFICATION:" at 192.594,32.02 h1.52
  text "MATERIALS AND WORKMANSHIP FOR ALL PCBS" at 211.009,32.02 h1.52
  text "TO MEET OR EXCEED THE REQUIREMENTS OF:" at 211.009,29.531 h1.52
  text "X" at 201.523,26.064 h1.52
  text "ANSI IPC-A-600F CLASS ->" at 205.053,26.064 h1.52
  text "X" at 246.685,26.064 h1.52
  text "2" at 249.706,26.064 h1.52
  text "1" at 241.705,26.026 h1.52
  text "3" at 258.698,26.026 h1.52
  text "X" at 201.575,22.013 h1.52
  text "UL 94V-0" at 205.053,22.013 h1.52
  text "X" at 222.2,22.013 h1.52
  text "RoHS" at 225.678,22.013 h1.52
  text "OTHER" at 242.046,22.013 h1.52
  text "PER ORDER" at 252.131,22.013 h1.52
  text "ADDITIONAL REQUIREMENTS:" at 192.594,18.431 h1.52
  text "MICROSECTION:" at 194.494,15.51 h1.52
  text "YES" at 217.499,15.51 h1.52
  text "REQUIRED" at 239.381,11.544 h1.52
  text "BARE BOARD ELEC. TEST:" at 194.494,11.472 h1.52
  text "NONE" at 227.659,11.472 h1.52
  text "X" at 236.155,11.472 h1.52
  text "PER ORDER" at 254.418,11.472 h1.52
  text "MANUFACTURER'S UL:" at 194.494,7.484 h1.52
  text "RAIL" at 224.103,7.375 h1.52
  text "METAL" at 236.595,7.375 h1.52
  text "X" at 246.126,7.366 h1.52
  text "SILK" at 249.592,7.375 h1.52
  text ".Layer_Name" at -80.594,-38.57 h1.52
M11 Gerber Information:
  lines w0.254: -102.667,-40.39 64.973,-40.39 ; -102.667,-35.226 65.024,-35.226 ; -102.667,-30.061 -102.667,-45.555 -0.94,-45.555 65.024,-45.555 65.024,-30.061 -102.654,-30.061 -102.654,-45.555 -62.636,-45.555 ; -40.056,-45.555 -40.056,-30.061 ; -7.874,-35.226 -7.874,-30.061 ; 13.462,-35.226 13.462,-30.061 ; 29.261,-45.72 29.261,-40.568
  text "ALL ARTWORK VIEWED FROM TOP SIDE" at -101.054,-33.418 h1.52
  text "BOARD #:" at -38.151,-33.418 h1.52
  text ".PRJ_Number" at -24.295,-33.418 h1.52
  text "REV:" at -2.845,-33.418 h1.52
  text ".PCB_Rev" at 4.559,-33.418 h1.52
  text "SVN REV:" at 18.44,-33.418 h1.52
  text ".VersionControl_RevNumber" at 31.293,-33.418 h1.52
  text "LAYER NAME =" at -101.054,-38.57 h1.52
  text "TID #:" at -38.151,-38.583 h1.52
  text ".TID" at -24.295,-38.583 h1.52
  text "PLOT NAME =" at -101.054,-43.798 h1.52
  text ".plot_File_Name" at -80.594,-43.798 h1.52
  text "GENERATED    :" at -38.1,-43.798 h1.52
  text ".Print_Date" at -16.015,-43.798 h1.52
  text ".Print_Time" at 2.502,-43.798 h1.52
  text "TEXAS INSTRUMENTS" at 34.62,-43.798 h1.52
M12 Stackup:
  drawing of 191 lines, arcs and shapes, not listed
  text "Layer" at 153.793,182.689 h1.52
  text "Name" at 164.052,182.689 h1.52
  text "Material" at 187.516,182.689 h1.52
  text "Thickness" at 209.201,182.689 h1.52
  text "Constant" at 225.555,182.689 h1.52
  text "Board Layer Stack" at 239.877,182.689 h1.52
  text "Top Overlay" at 164.052,179.641 h1.52
  text "Top Solder" at 164.052,176.594 h1.52
  text "Solder Resist" at 187.516,176.594 h1.52
  text "0.40mil" at 209.201,176.594 h1.52
  text "3.5" at 225.555,176.594 h1.52
  text "1" at 153.793,173.546 h1.52
  text "Top Layer" at 164.052,173.546 h1.52
  text "1.38mil" at 209.201,173.546 h1.52
  text "Dielectric1" at 164.052,170.498 h1.52
  text "FR-4" at 187.516,170.498 h1.52
  text "35.83mil" at 209.201,170.498 h1.52
  text "4.6" at 225.555,170.498 h1.52
  text "2" at 153.793,167.45 h1.52
  text "Bottom Layer" at 164.052,167.45 h1.52
  text "1.38mil" at 209.201,167.45 h1.52
  text "Bottom Solder" at 164.052,164.401 h1.52
  text "Solder Resist" at 187.516,164.401 h1.52
  text "0.40mil" at 209.201,164.401 h1.52
  text "3.5" at 225.555,164.401 h1.52
  text "Bottom Overlay" at 164.052,161.353 h1.52
  text ".Layer_Name" at -80.594,-38.57 h1.52
M13 Component Bodies Top:
  text ".Layer_Name" at -80.594,-38.57 h1.52
M14 Component Bodies Bottom:
  text ".Layer_Name" at -80.594,-38.57 h1.52
M15 Courtyards Top:
  text ".Layer_Name" at -80.594,-38.57 h1.52
M16 Courtyards Bottom:
  text ".Layer_Name" at -80.594,-38.57 h1.52
Drill Drawing:
  circle w0.254: c48.151,67.326 r0.702
  lines w0.254: 47.449,41.363 48.853,41.363 48.853,42.766 47.449,42.766 47.449,41.363 ; 47.449,44.871 47.8,44.871 48.151,44.521 48.502,44.871 48.853,44.871 48.502,45.222 48.853,45.573 48.502,45.573 48.151,45.924 47.8,45.573 47.449,45.573 47.8,45.222 47.449,44.871 ; 47.449,54.345 47.8,54.345 47.8,53.994 48.502,53.994 48.502,54.345 48.853,54.345 48.853,55.046 48.502,55.046 48.502,55.397 47.8,55.397 47.8,55.046 47.449,55.046 47.449,54.345 ; 47.73,54.485 47.941,54.485 47.941,54.274 48.362,54.274 48.362,54.485 48.572,54.485 48.572,54.906 48.362,54.906 48.362,55.116 47.941,55.116 47.941,54.906 47.73,54.906 47.73,54.485
  lines w0.305: 46.177,30.942 124.339,30.942 ; 46.177,75.15 124.339,75.15 ; 54.759,27.785 54.759,78.308 ; 63.192,27.785 63.192,78.308 ; 79.36,27.785 79.36,78.308 ; 85.943,27.785 85.943,78.308 ; 95.472,27.785 95.472,78.308 ; 113.87,27.785 113.87,78.308 ; 46.177,27.785 124.339,27.785 124.339,78.308 46.177,78.308 46.177,27.785
  text "Symbol" at 48.072,76.098 h1.83
  text "Quantity" at 55.706,76.098 h1.83
  text "Finished Hole Size" at 64.139,76.098 h1.83
  text "Plated" at 80.308,76.098 h1.83
  text "Hole Type" at 86.89,76.098 h1.83
  text "Drill Layer Pair" at 96.419,76.098 h1.83
  text "Tolerance" at 114.817,76.098 h1.83
  text "1" at 55.706,72.94 h1.52
  text "78.50mil (1.994mm)" at 64.139,72.94 h1.52
  text "NPTH" at 80.308,72.94 h1.52
  text "Round" at 86.89,72.94 h1.52
  text "Top Layer - Bottom Layer" at 96.419,72.94 h1.52
  text "E" at 47.43,72.686 h1.4
  text "20" at 55.706,69.782 h1.52
  text "7.87mil (0.200mm)" at 64.139,69.782 h1.52
  text "PTH" at 80.308,69.782 h1.52
  text "Round" at 86.89,69.782 h1.52
  text "Top Layer - Bottom Layer" at 96.419,69.782 h1.52
  text "H" at 47.43,69.529 h1.4
  text "8" at 55.706,66.625 h1.52
  text "8.00mil (0.203mm)" at 64.139,66.625 h1.52
  text "PTH" at 80.308,66.625 h1.52
  text "Round" at 86.89,66.625 h1.52
  text "Top Layer - Bottom Layer" at 96.419,66.625 h1.52
  text "239" at 55.706,63.467 h1.52
  text "12.00mil (0.305mm)" at 64.139,63.467 h1.52
  text "PTH" at 80.308,63.467 h1.52
  text "Round" at 86.89,63.467 h1.52
  text "Top Layer - Bottom Layer" at 96.419,63.467 h1.52
  text "F" at 47.43,63.213 h1.4
  text "19" at 55.706,60.309 h1.52
  text "14.96mil (0.380mm)" at 64.139,60.309 h1.52
  text "PTH" at 80.308,60.309 h1.52
  text "Round" at 86.89,60.309 h1.52
  text "Top Layer - Bottom Layer" at 96.419,60.309 h1.52
  text "I" at 47.663,60.055 h1.4
  text "1" at 55.706,57.151 h1.52
  text "16.00mil (0.406mm)" at 64.139,57.151 h1.52
  text "PTH" at 80.308,57.151 h1.52
  text "Round" at 86.89,57.151 h1.52
  text "Top Layer - Bottom Layer" at 96.419,57.151 h1.52
  text "J" at 47.43,56.898 h1.4
  text "6" at 55.706,53.994 h1.52
  text "25.59mil (0.650mm)" at 64.139,53.994 h1.52
  text "PTH" at 80.308,53.994 h1.52
  text "Round" at 86.89,53.994 h1.52
  text "Top Layer - Bottom Layer" at 96.419,53.994 h1.52
  text "1" at 55.706,50.836 h1.52
  text "28.00mil (0.711mm)" at 64.139,50.836 h1.52
  text "PTH" at 80.308,50.836 h1.52
  text "Round" at 86.89,50.836 h1.52
  text "Top Layer - Bottom Layer" at 96.419,50.836 h1.52
  text "G" at 47.43,50.582 h1.4
  text "28" at 55.706,47.678 h1.52
  text "29.53mil (0.750mm)" at 64.139,47.678 h1.52
  text "PTH" at 80.308,47.678 h1.52
  text "Round" at 86.89,47.678 h1.52
  text "Top Layer - Bottom Layer" at 96.419,47.678 h1.52
  text "A" at 47.43,47.424 h1.4
  text "2" at 55.706,44.521 h1.52
  text "35.43mil (0.900mm)" at 64.139,44.521 h1.52
  text "PTH" at 80.308,44.521 h1.52
  text "Round" at 86.89,44.521 h1.52
  text "Top Layer - Bottom Layer" at 96.419,44.521 h1.52
  text "15" at 55.706,41.363 h1.52
  text "40.00mil (1.016mm)" at 64.139,41.363 h1.52
  text "PTH" at 80.308,41.363 h1.52
  text "Round" at 86.89,41.363 h1.52
  text "Top Layer - Bottom Layer" at 96.419,41.363 h1.52
  text "2" at 55.706,38.205 h1.52
  text "59.06mil (1.500mm)" at 64.139,38.205 h1.52
  text "PTH" at 80.308,38.205 h1.52
  text "Round" at 86.89,38.205 h1.52
  text "Top Layer - Bottom Layer" at 96.419,38.205 h1.52
  text "D" at 47.43,37.951 h1.4
  text "4" at 55.706,35.047 h1.52
  text "66.93mil (1.700mm)" at 64.139,35.047 h1.52
  text "PTH" at 80.308,35.047 h1.52
  text "Round" at 86.89,35.047 h1.52
  text "Top Layer - Bottom Layer" at 96.419,35.047 h1.52
  text "C" at 47.43,34.794 h1.4
  text "2" at 55.706,31.89 h1.52
  text "125.00mil (3.175mm)" at 64.139,31.89 h1.52
  text "PTH" at 80.308,31.89 h1.52
  text "Round" at 86.89,31.89 h1.52
  text "Top Layer - Bottom Layer" at 96.419,31.89 h1.52
  text "K" at 47.43,31.636 h1.4
  text "348 Total" at 55.706,28.732 h1.52
  text ".Layer_Name" at -80.594,-38.57 h1.52

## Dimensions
0,0 to -6.68,87.706 on M2 Board Dimensions
0,-2.362 to 40.005,-4.496 on M2 Board Dimensions
-95.25,-26.924 to -69.85,-26.924 on M2 Board Dimensions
